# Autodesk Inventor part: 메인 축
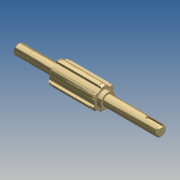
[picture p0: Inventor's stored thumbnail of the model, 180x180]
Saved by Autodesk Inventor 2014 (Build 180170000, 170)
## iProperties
Created: 2015-11
Part Number: 메인 축
Document SubType Name: 모델링
Designer: mdu
Mass: 168.566 g
Surface Area: 72.5104 cm^2
Volume: 21.4461 cm^3
Density: 7.86 g/cm^3
Material: 강철, 연강
Appearance: 강철
변환 표준: STEP AP214IS
파일 이름: C:\Users\SeoGD\Desktop\?쒗뿕\硫붿씤 異?.stp
전처리기: Build: 253, Release: 2010 SP1 - Date: Wed 07/29/2009
전송 단위: 밀리미터
불확실성: 0.01
Author: mdu
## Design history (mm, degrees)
sketch "스케치1"
  geometry: L1 (-69.5, 0)-(69.5, 0); L2 (69.5, 0)-(69.5, 5); L3 (69.5, 5)-(55.5, 5); L4 (55.5, 5)-(55.5, 4.8); L5 (55.5, 4.8)-(54.35, 4.8); L6 (54.35, 4.8)-(54.35, 5); L7 (54.35, 5)-(30.5, 5); L8 (30.5, 5)-(30.5, 9); L9 (30.5, 9)-(-13.5, 9); L10 (-13.5, 9)-(-13.5, 7); L11 (-13.5, 7)-(-17.5, 7); L12 (-17.5, 7)-(-17.5, 5); L13 (-17.5, 5)-(-69.5, 5); L14 (-69.5, 5)-(-69.5, 0); 2 further points
  constraints: 28 end point, 9 parallel, 4 collinear, 2 perpendicular, 1 coincident, 1 horizontal, 1 midpoint
  dimensions: "d2" = 1.15 distance between parallel lines of L6 L4; "d3" = 10 diameter of L3 L1; "d4" = 9.6 diameter of L5 L1; "d6" = 44 distance between parallel lines of L10 L8; "d7" = 4 distance between parallel lines of L12 L10; "d8" = 14 diameter of L11 L1; "d9" = 18 diameter of L9 L1; "d33" = 52 distance from line of L12.end L14; "d37" = 39 distance between parallel lines of L8 L2; "d38" = 14 distance between parallel lines of L2 L4
revolve "회전1" sketch "스케치1" stored, may be unused: angle "d10" = 90 deg
sketch "스케치2"
  geometry: L1 (2.5, 10.712)-(2.5, 8.646); L2 (-2.5, 10.712)-(-2.5, 8.646); A1 r 9 centre (0, 0) between (2.5, 8.646) and (-2.5, 8.646) reference; A2 r 11 centre (0, 0) between (2.5, 10.712) and (-2.5, 10.712); 1 further point
  constraints: 4 end point, 4 point on circle, 2 parallel, 1 centre point, 1 coincident, 1 vertical
  dimensions: "d11" = 22 diameter of A2; "d12" = 5 distance between parallel lines of L1 L2
extrude "돌출1" join sketch "스케치2" stored distance "d13" = 10; taper "d14" = 0 deg
chamfer "모따기1" distance "d15" = 1; stored, may be unused: second distance "d16" = 2, angle "d17" = 45 deg
node "작업 평면1"
node "작업 평면2"
sketch "스케치3"
  geometry: L1 (2.5, 10.712)-(2.5, 10.198); L2 (-2.5, 10.712)-(-2.5, 10.198); A1 r 11 centre (0, 0) between (2.5, 10.712) and (-2.5, 10.712) reference; A2 r 10.5 centre (0, 0) between (2.5, 10.198) and (-2.5, 10.198); 1 further point
  constraints: 4 end point, 2 point on circle, 1 centre point, 1 coincident, 1 parallel, 1 vertical
  dimensions: "d19" = 21 diameter of A2
extrude "돌출2" cut sketch "스케치3" distance "d20" = 1.35; taper "d21" = 0 deg
node "작업 평면3"
sketch "스케치4"
  geometry: L1 (-26, -5)-(-26, 5) reference; L2 (-26, 1.5)-(-12.5, 1.5); L3 (-12.5, -1.5)-(-26, -1.5); A1 r 1.5 centre (-12.5, 0) between (-12.5, -1.5) and (-12.5, 1.5); 2 further points
  constraints: 4 end point, 2 perpendicular, 2 point on circle, 2 point on line, 2 tangent, 1 centre point, 1 horizontal alignment, 1 midpoint
  dimensions: "d25" = 3 distance between parallel lines of L3 L2; "d26" = 15 dimension on A1 L1
extrude "돌출3" cut sketch "스케치4" distance "d27" = 1.8; taper "d28" = 0 deg
chamfer "모따기2" distance "d29" = 1; stored, may be unused: second distance "d30" = 2, angle "d31" = 45 deg
node "솔리드1"
node "솔리드 본체"
node "곡면 본체"
mirror "대칭1"
pattern_circular "원형 패턴1" dims "d23" = 360 deg
node "솔리드2"
other parameters: "d18" = -1.65
